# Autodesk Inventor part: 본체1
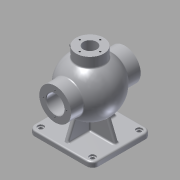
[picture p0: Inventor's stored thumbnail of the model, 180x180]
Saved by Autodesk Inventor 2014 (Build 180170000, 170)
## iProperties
Created: 2015-10
Part Number: 본체1
Material: 알루미늄 6061
Document SubType Name: Modeling
Designer: youjin11
Density: 2.71 g/cm^3
Appearance: 알루미늄 - 평지
Mass: 2158.12 g
Surface Area: 1075.22 cm^2
Volume: 796.355 cm^3
Author: youjin11
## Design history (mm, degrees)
sketch "스케치1"
  geometry: L1 (-62.5, -57.5)-(62.5, -57.5); L2 (62.5, -57.5)-(62.5, 57.5); L3 (62.5, 57.5)-(-62.5, 57.5); L4 (-62.5, 57.5)-(-62.5, -57.5); L5 (-62.5, -57.5)-(62.5, 57.5); L6 (62.5, -57.5)-(-62.5, 57.5); 1 further point
  constraints: 12 end point, 2 midpoint, 2 parallel, 1 horizontal, 1 perpendicular
  dimensions: "d0" = 125 distance of L3.end L2.end; "d1" = 115 distance of L2.end L1.end
extrude "돌출1" new body sketch "스케치1" distance "d2" = 10; taper "d3" = 0 deg
fillet "모깎기1" dims "d4" = 12
sketch "스케치2"
  geometry: C1 r 4 at (-50.5, 45.5); C2 r 4 at (50.5, 45.5); C3 r 4 at (50.5, -45.5); C4 r 4 at (-50.5, -45.5); A1 r 12 centre (-50.5, -45.5) between (-62.5, -45.5) and (-50.5, -57.5) reference; A2 r 12 centre (50.5, -45.5) between (50.5, -57.5) and (62.5, -45.5) reference; A3 r 12 centre (50.5, 45.5) between (62.5, 45.5) and (50.5, 57.5) reference; A4 r 12 centre (-50.5, 45.5) between (-50.5, 57.5) and (-62.5, 45.5) reference; 1 further point
  constraints: 4 centre point, 4 coincident
  dimensions: "d5" = 8 diameter of C1; "d6" = 8 diameter of C2; "d7" = 8 diameter of C3; "d8" = 8 diameter of C4
extrude "돌출2" cut sketch "스케치2" stored distance "d9" = 10; taper "d10" = 0 deg
sketch "스케치3"
  geometry: C1 r 4 at (50.5, -45.5) reference; C2 r 4 at (-50.5, 45.5) reference; C3 r 4 at (-50.5, -45.5) reference; C4 r 6 at (-50.5, 45.5); C5 r 6 at (50.5, -45.5); C6 r 6 at (-50.5, -45.5); C7 r 6 at (50.5, 45.5); A1 r 12 centre (-50.5, -45.5) between (-62.5, -45.5) and (-50.5, -57.5) reference; A2 r 12 centre (50.5, -45.5) between (50.5, -57.5) and (62.5, -45.5) reference; A3 r 12 centre (-50.5, 45.5) between (-50.5, 57.5) and (-62.5, 45.5) reference; A4 r 12 centre (50.5, 45.5) between (62.5, 45.5) and (50.5, 57.5) reference; 1 further point
  constraints: 4 centre point, 4 coincident
  dimensions: "d11" = 12 diameter of C4; "d13" = 12 diameter of C5; "d14" = 12 diameter of C6; "d17" = 12 diameter of C7
extrude "돌출3" cut sketch "스케치3" distance "d15" = 3; taper "d16" = 0 deg
extrude "돌출4" cut sketch "스케치3" distance "d18" = 3; taper "d19" = 0 deg
sketch "스케치4"
  geometry: L1 (50.5, 0)-(-50.5, 0) reference; L2 (-53, 85)-(53, 85); A1 r 53 centre (0, 85) between (53, 85) and (-53, 85); 1 further point
  constraints: 2 end point, 2 point on circle, 1 centre point, 1 midpoint, 1 parallel, 1 vertical alignment
  dimensions: "d22" = 53 radius of A1; "d23" = 85 distance from line of L1 A1.centre
revolve "회전1" sketch "스케치4" stored, may be unused: angle "d24" = 90 deg
node "작업 평면1"
sketch "스케치5"
  geometry: C1 r 31 at (0, 85); 1 further point
  constraints: 1 centre point
  dimensions: "d27" = 62 diameter of C1; "d28" = 85 distance of point (0, 0) C1.centre
extrude "돌출5" join sketch "스케치5" stored distance "d29" = 10; taper "d30" = 0 deg
node "작업 평면3"
sketch "스케치6"
  geometry: C1 r 27 at (0, 0); 1 further point
  constraints: 1 centre point, 1 coincident
  dimensions: "d32" = 54 diameter of C1
extrude "돌출6" join sketch "스케치6" stored distance "d33" = 10; taper "d34" = 0 deg
sketch "스케치7"
  geometry: C1 r 31 at (0, 0) reference; C2 r 17.5 at (0, 0); 1 further point
  constraints: 1 centre point, 1 coincident
  dimensions: "d35" = 35 diameter of C2
extrude "돌출7" cut sketch "스케치7" stored distance "d36" = 10; taper "d37" = 0 deg
sketch "스케치8"
  geometry: C1 r 27 at (0, 0) reference; C2 r 13 at (0, 0)
  constraints: 1 centre point, 1 coincident
  dimensions: "d38" = 26 diameter of C2
extrude "돌출8" cut sketch "스케치8" distance "d39" = 60; taper "d40" = 0 deg
sketch "스케치9"
  geometry: C1 r 31 at (0, 0) reference; A1 r 22.5 centre (0, 0) between (0, 22.5) and (-22.5, 0); 3 further points
  constraints: 4 point on circle, 1 centre point, 1 coincident
  dimensions: "d41" = 45 diameter of A1
hole "구멍1" sketch "스케치9" at (-22.5, 0), (0, 22.5), (22.5, 0), (0, -22.5) diameter "d42" = 3.459; stored, may be unused: countersink angle "d46" = 82 deg, drill point angle "d48" = 118 deg; dims "d43" = 12, "d44" = 3.023, "d45" = 2, "d47" = 15
sketch "스케치10"
  geometry: C1 r 31 at (0, 0) reference; A1 r 24 centre (0, 0) between (0, 24) and (-24, 0); 3 further points
  constraints: 4 point on circle, 1 centre point, 1 coincident
  dimensions: "d49" = 48 diameter of A1
hole "구멍2" sketch "스케치10" at (0, 24), (-24, 0), (0, -24), (24, 0) diameter "d50" = 3.459; stored, may be unused: countersink angle "d54" = 82 deg, drill point angle "d56" = 118 deg; dims "d51" = 16, "d52" = 3.023, "d53" = 2, "d55" = 19
sketch "스케치11"
  geometry: C1 r 27 at (0, 0) reference; A1 r 20 centre (0, 0) between (0, 20) and (-20, 0); 2 further points
  constraints: 4 point on circle, 1 centre point, 1 coincident
  dimensions: "d57" = 40 diameter of A1
hole "구멍3" sketch "스케치11" at (0, 20), (-20, 0), (0, -20), (20, 0) diameter "d58" = 3.459; stored, may be unused: countersink angle "d62" = 82 deg, drill point angle "d64" = 118 deg; dims "d59" = 9, "d60" = 3.023, "d61" = 2, "d63" = 11
sketch "스케치17"
  geometry: L1 (45.5, 10)-(-45.5, 10) reference; L2 (47.5, 10)-(33.719, 44.109); L3 (-57.5, 0)-(-57.5, 10) reference; L4 (57.5, 10)-(57.5, 0) reference; L5 (39.5, 10)-(51.5, 10) reference; L6 (-33.719, 44.109)-(-47.5, 10); A1 r 53 centre (0, 85) between (42.988, 116) and (42.988, 54) reference; 1 further point
  constraints: 4 end point, 2 point on circle, 2 point on line
  dimensions: "d68" = 10 distance from line of L4 L2.start; "d69" = 68 deg angle of L5 L2; "d72" = 22 deg angle of L6 L3; "d73" = 10 distance from line of L6.end L3
sketch "스케치18"
  geometry: L1 (-50.5, -57.5)-(50.5, -57.5) reference; L2 (62.5, -45.5)-(62.5, 45.5) reference; L3 (50.5, 57.5)-(-50.5, 57.5) reference; L4 (-62.5, 45.5)-(-62.5, -45.5) reference; L5 (0, 57.5)-(0, -57.5); C1 r 6 at (50.5, -45.5) reference; C2 r 6 at (-50.5, 45.5) reference; C3 r 6 at (-50.5, -45.5) reference; C4 r 6 at (50.5, 45.5) reference; A1 r 12 centre (-50.5, -45.5) between (-62.5, -45.5) and (-50.5, -57.5) reference; A2 r 12 centre (50.5, -45.5) between (50.5, -57.5) and (62.5, -45.5) reference; A3 r 12 centre (50.5, 45.5) between (62.5, 45.5) and (50.5, 57.5) reference; A4 r 12 centre (-50.5, 45.5) between (-50.5, 57.5) and (-62.5, 45.5) reference; 1 further point
  constraints: 2 end point, 2 midpoint
sketch "스케치19"
  geometry: L1 (-33.719, 44.109)-(-47.5, 10) reference; L2 (47.5, 10)-(33.719, 44.109) reference; L3 (45.5, 10)-(-45.5, 10) reference; L4 (57.5, 10)-(-57.5, 10) reference; A1 r 53 centre (0, 85) between (42.988, 116) and (42.988, 54) reference; 3 further points
extrude "돌출9" join sketch "스케치19" stored distance "d74" = 8; taper "d75" = 0 deg
sketch "스케치21"
  geometry: L1 (-4, -47.5)-(-4, 47.5) reference; L2 (-4, 47.5)-(4, 47.5) reference; L3 (4, 47.5)-(4, -47.5) reference; L4 (4, -47.5)-(-4, -47.5) reference; L5 (-50.5, -57.5)-(50.5, -57.5) reference; L6 (62.5, -45.5)-(62.5, 45.5) reference; L7 (50.5, 57.5)-(-50.5, 57.5) reference; L8 (-62.5, 45.5)-(-62.5, -45.5) reference; L9 (-62.5, 0)-(62.5, 0); C1 r 6 at (50.5, -45.5) reference; C2 r 6 at (-50.5, 45.5) reference; C3 r 6 at (-50.5, -45.5) reference; C4 r 6 at (50.5, 45.5) reference; A1 r 12 centre (-50.5, -45.5) between (-62.5, -45.5) and (-50.5, -57.5) reference; A2 r 12 centre (50.5, -45.5) between (50.5, -57.5) and (62.5, -45.5) reference; A3 r 12 centre (50.5, 45.5) between (62.5, 45.5) and (50.5, 57.5) reference; A4 r 12 centre (-50.5, 45.5) between (-50.5, 57.5) and (-62.5, 45.5) reference; 1 further point
  constraints: 2 end point, 2 midpoint
sketch "스케치22"
  geometry: L1 (62.5, 10)-(-62.5, 10) reference; L2 (-37.379, 47.426)-(-52.5, 10); L3 (37.379, 47.426)-(52.5, 10); L4 (-62.5, 0)-(-62.5, 10) reference; L5 (62.5, 10)-(62.5, 0) reference; A1 r 53 centre (0, 85) between (-27, 130.607) and (27, 130.607) reference; 1 further point
  constraints: 4 end point, 2 point on circle, 2 point on line
  dimensions: "d76" = 22 deg angle of L4 L2; "d77" = 22 deg angle of L5 L3; "d78" = 10 distance of L2.end L1.end; "d79" = 10 distance of L1.start L3.end
extrude "돌출10" join sketch "스케치22" stored distance "d80" = 8; taper "d81" = 0 deg
fillet "모깎기2" dims "d82" = 3
chamfer "모따기1" distance "d83" = 1; stored, may be unused: second distance "d84" = 2, angle "d85" = 45 deg
sketch "스케치24"
  geometry: L1 (-45, 85)-(45, 85); A1 r 45 centre (0, 85) between (45, 85) and (-45, 85); 1 further point
  constraints: 2 end point, 2 point on circle, 1 centre point
  dimensions: "d87" = 45 radius of A1
revolve "회전2" sketch "스케치24" stored, may be unused: angle "d88" = 90 deg
node "작업 평면4"
sketch "스케치25"
  geometry: L1 (-13.921, -4.6)-(13.921, -4.6); L2 (13.921, -4.6)-(13.921, -8.539); L3 (13.921, -8.539)-(-13.921, -8.539); L4 (-13.921, -8.539)-(-13.921, -4.6); 1 further point
  constraints: 2 other
extrude "돌출11" join sketch "스케치25" stored distance "d89" = 10; taper "d90" = 0 deg
node "솔리드1"
mirror "대칭1"
node "작업 평면2"
other parameters: "d25" = -68
